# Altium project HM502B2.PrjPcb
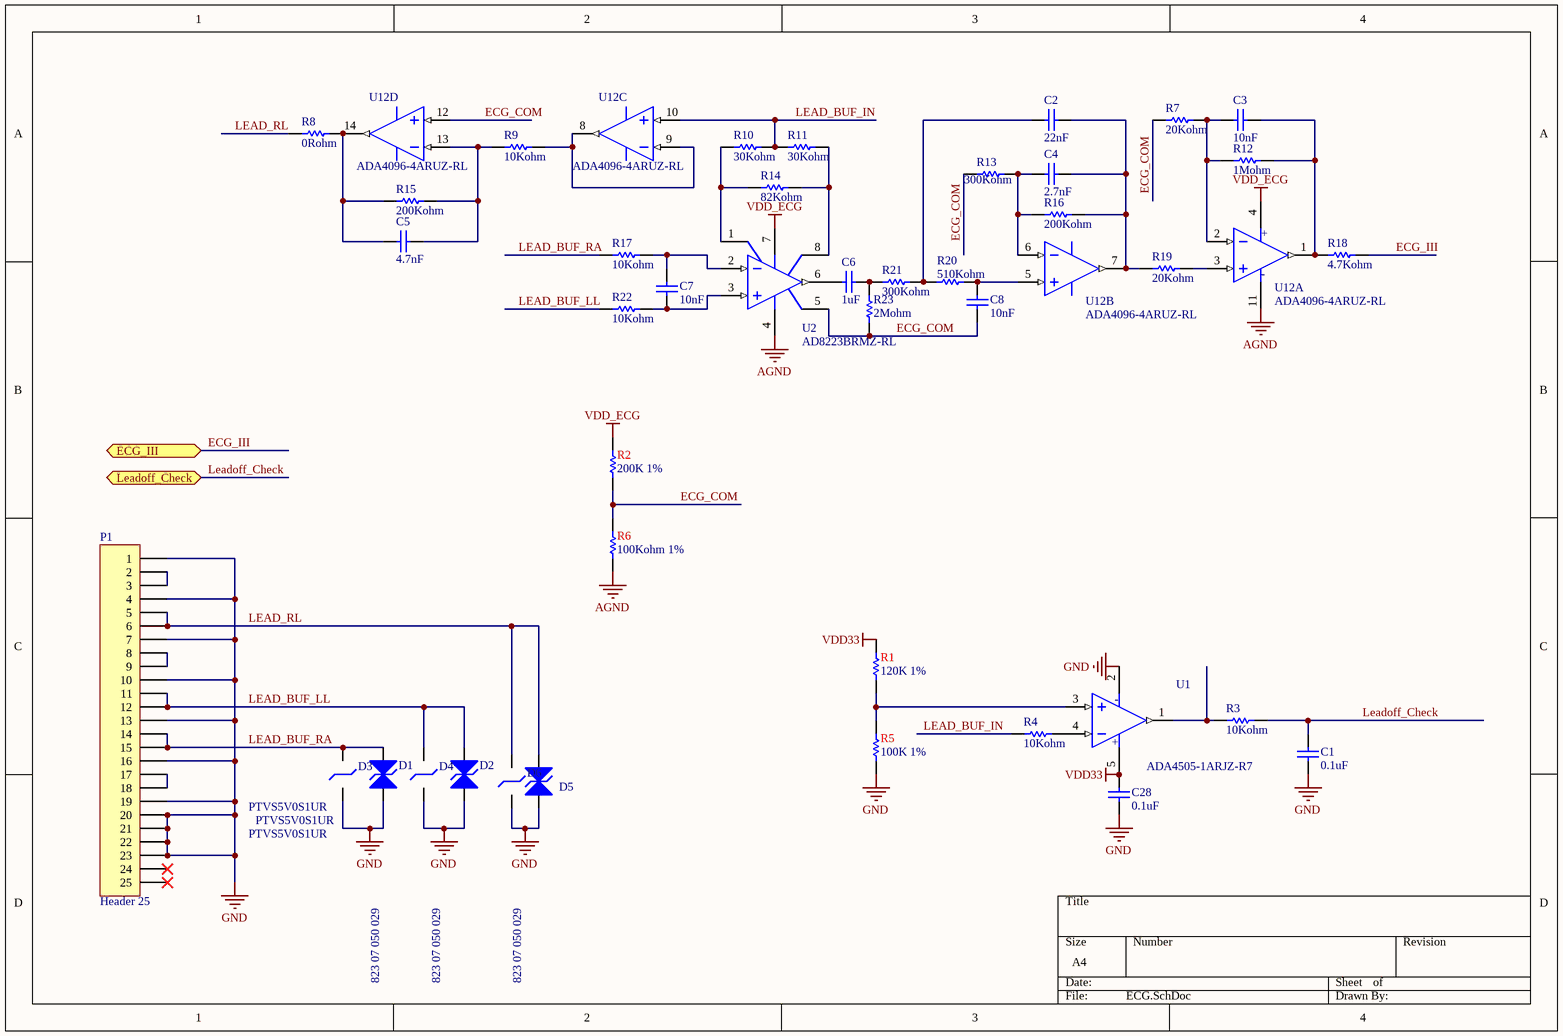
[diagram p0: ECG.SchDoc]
4 sheets, 138 parts. Net scope: flat (ports and power ports of the same name join across sheets).
Board files: HM502B2.PcbDoc, HM502B2拼板.PcbDoc
Sheets:
  ECG.SchDoc
  MCU.SchDoc
  POWER.SchDoc
  UART_BT.SchDoc

## Sheet ECG.SchDoc
size A4

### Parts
C1  0.1uF  [C0402]
C2  22nF  [C0402]
C3  10nF  [C0402]
C4  2.7nF  [C0402]
C5  4.7nF  [C0402]
C6  1uF  [C0402]
C7  10nF  [C0402]
C8  10nF  [C0402]
C28  0.1uF  [C0402]
D1  823 07 050 029  [R0402]
D2  823 07 050 029  [R0402]
D3  PTVS5V0S1UR  [SOD123]
D4  PTVS5V0S1UR  [SOD123]
D5  823 07 050 029  [R0402]
D6  PTVS5V0S1UR  [SOD123]
P1  Header 25  [mini-HDMI_post]
R1  120K 1%  [R0402]
R2  200K 1%  [R0402]
R3  10Kohm  [R0402]
R4  10Kohm  [R0402]
R5  100K 1%  [R0402]
R6  100Kohm 1%  [R0402]
R7  20Kohm  [R0402]
R8  0Rohm  [R0402]
R9  10Kohm  [R0402]
R10  30Kohm  [R0402]
R11  30Kohm  [R0402]
R12  1Mohm  [R0402]
R13  300Kohm  [R0402]
R14  82Kohm  [R0402]
R15  200Kohm  [R0402]
R16  200Kohm  [R0402]
R17  10Kohm  [R0402]
R18  4.7Kohm  [R0402]
R19  20Kohm  [R0402]
R20  510Kohm  [R0402]
R21  300Kohm  [R0402]
R22  10Kohm  [R0402]
R23  2Mohm  [R0402]
U1  ADA4505-1ARJZ-R7  [SOT-23-5]
U2  AD8223BRMZ-RL  [MSOP-8]
U12  ADA4096-4ARUZ-RL  [TSSOP-14]  (parts A,B,C,D of 4)

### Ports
ECG_III, Leadoff_Check

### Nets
AGND: R6.1 U2.4(V-) U12.11(V-)
GND: C1.2 C28.2 D1.2(K) D2.1(K) D3.1(K) D4.1(K) D5.1(K) D6.1(K) P1.1 P1.4 P1.7 P1.10 P1.13 P1.16 P1.19 P1.20 P1.21 P1.22 P1.23 R5.1 U1.2(V-)
VDD33: C28.1 R1.2 U1.5(V+)
VDD_ECG: R2.2 U2.7(V+) U12.4(V+)
ECG_COM: C8.2 R2.1 R6.2 R7.1 R13.1 R23.1 U2.5(NC) U12.12(IN+)
ECG_III: R18.2 ; port ECG_III
LEAD_BUF_IN: R4.1 R10.2 R11.1 U12.10(IN+)
LEAD_BUF_LL: D2.2(K) D4.2(K) P1.11 P1.12 R22.1
LEAD_BUF_RA: D1.1(K) D3.2(K) P1.14 P1.15 R17.1
LEAD_RL: D5.2(K) D6.2(K) P1.5 P1.6 R8.1
Leadoff_Check: C1.1 R3.2 ; port Leadoff_Check
NetC2_1: C2.1 R20.1 R21.2
NetC2_2: C2.2 C4.2 R16.2 R19.1 U12.7(OUT)
NetC3_1: C3.1 R7.2 R12.1 U12.2(IN-)
NetC3_2: C3.2 R12.2 R18.1 U12.1(OUT)
NetC4_1: C4.1 R13.2 R16.1 U12.6(IN-)
NetC5_1: C5.1 R8.2 R15.1 U12.14(OUT)
NetC5_2: C5.2 R9.1 R15.2 U12.13(IN-)
NetC6_1: C6.1 U2.6(OUT)
NetC6_2: C6.2 R21.1 R23.2
NetC7_1: C7.1 R17.2 U2.2(IN-)
NetC7_2: C7.2 R22.2 U2.3(IN+)
NetC8_1: C8.1 R20.2 U12.5(IN+)
NetP1_2: P1.2 P1.3
NetP1_8: P1.8 P1.9
NetP1_17: P1.17 P1.18
NetR1_1: R1.1 R5.2 U1.3(IN+)
NetR3_1: R3.1 U1.1(OUT)
NetR4_2: R4.2 U1.4(IN-)
NetR9_2: R9.2 U12.8(OUT) U12.9(IN-)
NetR10_1: R10.1 R14.1 U2.1(VOSTRIM)
NetR11_2: R11.2 R14.2 U2.8(VOSTRIM)
NetR19_2: R19.2 U12.3(IN+)

Not connected (* = marked no-connect by the designer): P1 24* 25*

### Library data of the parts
C1 C3 C7 C8 C28 = Cap Semi: 0402,50V,10nF,10%,X7R,0.55mm; 名称: 贴片电容; 物料编号: 11U2103K00; 生产厂家型号: CC0402KRX7R9BB103; 生产厂家: 国巨
C2 = Cap Semi: 0402,10V,22nF,10% ,X5R,0.55mm; 名称: 贴片电容; 物料编号: 11E2223K0F; 生产厂家型号: GRM155R61A223KA01D; 生产厂家: MURATA
C4 = Cap Semi: 0402,50V,2.7nF,10%,X7R,0.55mm; 名称: 贴片电容; 物料编号: 11U2272K00; 生产厂家型号: CC0402KRX7R9BB272; 生产厂家: 国巨
C5 = Cap Semi: 0402,50V,4.7nF,10% ,X7R,0.55mm; 名称: 贴片电容; 物料编号: 11U2472K00; 生产厂家型号: CC0402KRX7R9BB472; 生产厂家: 国巨
C6 = Cap Semi: 0402,16V,1uF,10%,X5R,0.55mm; 名称: 贴片电容; 物料编号: 11E2105K00; 生产厂家型号: CC0402KRX5R7BB105; 生产厂家: 国巨
D1 D2 D5 = TPD1E10B06: ESD,0402,5V,0.2pF,0.05uA; 物料编号: 141D002837; 生产厂家: WE
D3 D4 D6 = ESD7951S-D-92833: TVS ESD,SOD923,5V,0.5pF,1uA; 名称: 贴片TVS管; 备注: Vrwm=5V,VBR (V)=6.2,VCL (V)=9.2,IRM (μA)=5; 生产厂家: NXP
P1 = Header 25: Header, 25-Pin
R1-R6 R8 R9 R17 R22 = Res Semi: 0402,10Kohm,1%,1/16W,0.40mm; 名称: 贴片电阻; 物料编号: 1121002F00; 生产厂家型号: RC0402FR-0710KL; 生产厂家: 国巨
R7 R19 = Res Semi: 0402,20Kohm,1%,1/16W,0.40mm; 名称: 贴片电阻; 物料编号: 1122002F00; 生产厂家型号: RC0402FR-0720KL; 生产厂家: 国巨
R10 R11 = Res Semi: 0402,30Kohm,1%,1/16W,0.40mm; 名称: 贴片电阻; 物料编号: 1123002F00; 生产厂家型号: RC0402FR-0730KL; 生产厂家: 国巨
R12 = Res Semi: 0402,1Mohm,1%,1/16W,0.40mm; 名称: 贴片电阻; 物料编号: 1121004F00; 生产厂家型号: RC0402FR-071ML; 生产厂家: 国巨
R13 R21 = Res Semi: 0402,300Kohm,1%,1/16W,0.40mm; 名称: 贴片电阻; 物料编号: 1123003F00; 生产厂家型号: RC0402FR-07300KL; 生产厂家: 国巨
R14 = Res Semi: 0402,82Kohm,1%,1/16W,0.40mm; 名称: 贴片电阻; 物料编号: 1128202F00; 生产厂家型号: RC0402FR-0782KL; 生产厂家: 国巨
R15 R16 = Res Semi: 0402,200Kohm,1%,1/16W,0.40mm; 名称: 贴片电阻; 物料编号: 1122003F00; 生产厂家型号: RC0402FR-07200KL; 生产厂家: 国巨
R18 = Res Semi: 0402,3Kohm,1%,1/16W,0.40mm; 名称: 贴片电阻; 物料编号: 1124701J00; 生产厂家型号: RC0402JR-074K7L; 生产厂家: 国巨
R20 = Res Semi: 0402,510Kohm,1%,1/16W,0.40mm; 名称: 贴片电阻; 物料编号: 1125103F00; 生产厂家型号: RC0402FR-07510KL; 生产厂家: 国巨
R23 = Res Semi: 0402,2Mohm,1%,1/16W,0.40mm; 名称: 贴片电阻; 物料编号: 1122004F00; 生产厂家型号: RC0402FR-072ML; 生产厂家: 国巨
U1 = OPA348: 50KHz,10uA,SOT-23-5; 名称: 轨至轨运算放大器; 物料编号: 13CB02220X; 生产厂家: ADI
U2 = OP05CP: 单电源、轨到轨、仪表放大器,MSOP-8; 名称: 仪表放大器; 物料编号: 13CC02190X; 生产厂家: ADI
U12 = LP324: 4通道,微功耗,TSSOP-14; 名称: 运放; 物料编号: 13C302200X; 生产厂家: ADI

## Sheet MCU.SchDoc
size A3
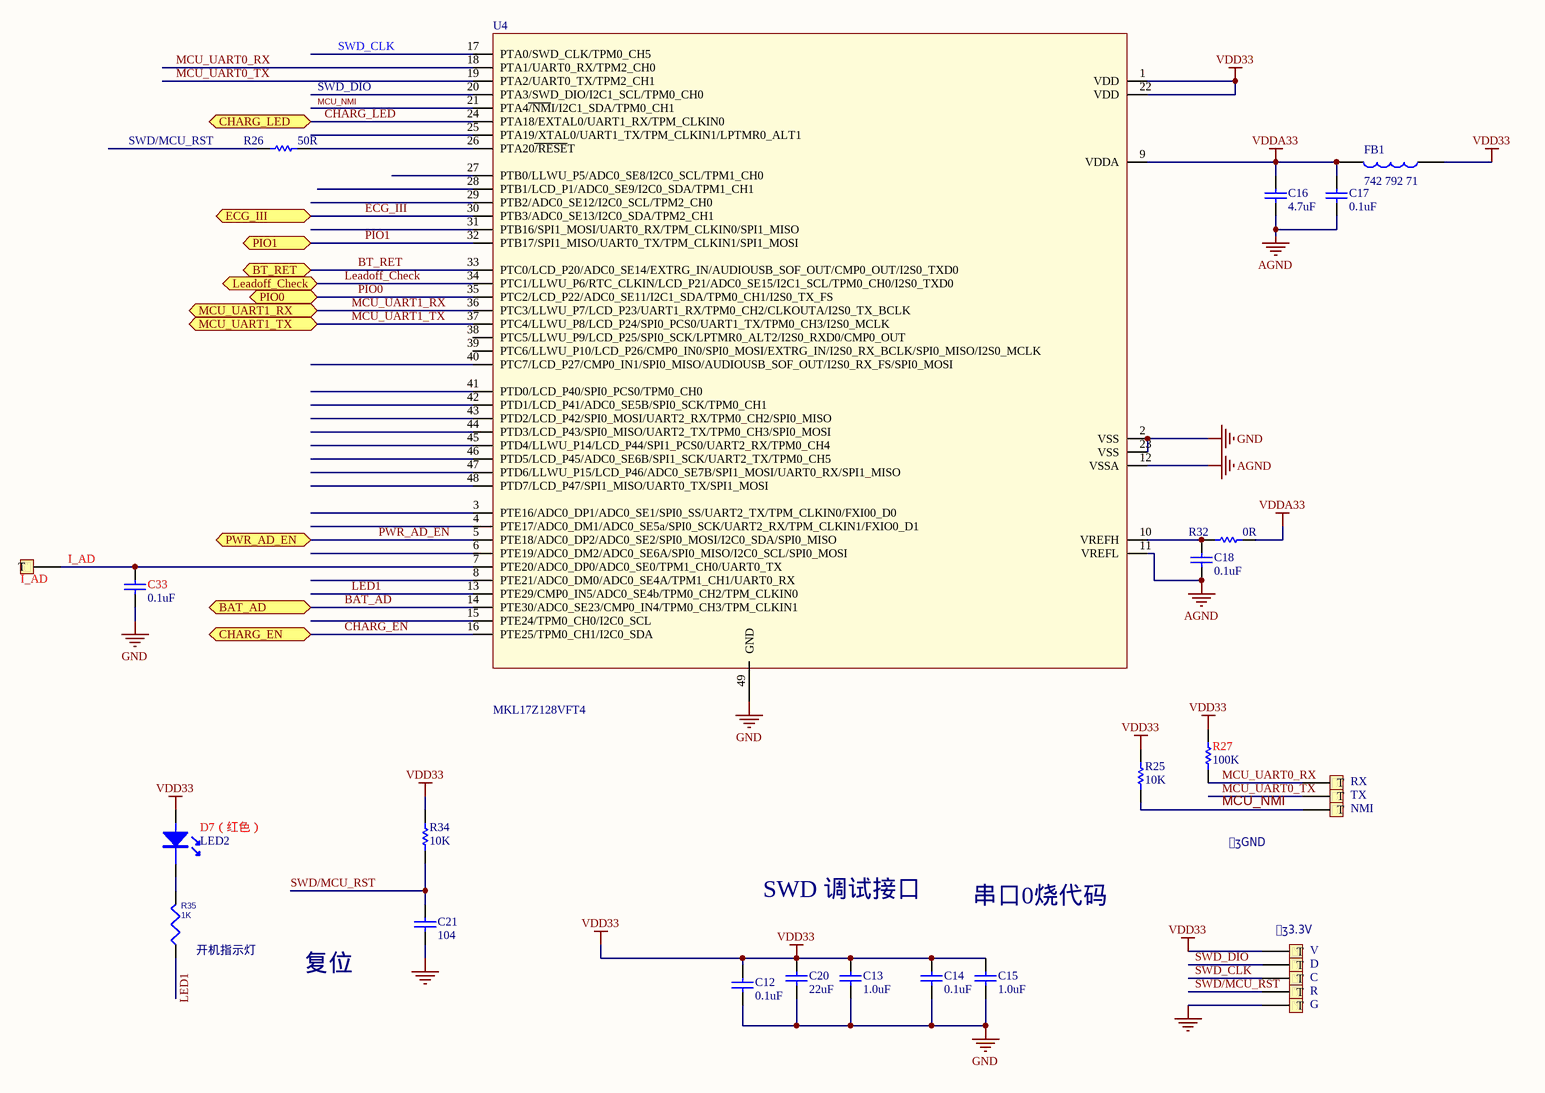
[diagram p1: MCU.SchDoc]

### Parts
C  TEST  [TP - 1.27mm]  (value not drawn)
C12  0.1uF  [C0402]
C13  1.0uF  [C0402]
C14  0.1uF  [C0402]
C15  1.0uF  [C0402]
C16  4.7uF  [C0805]
C17  0.1uF  [C0402]
C18  0.1uF  [C0402]
C20  22uF  [C0805]
C21  104  [C0402]
C33  0.1uF  [C0402]
D  TEST  [TP - 1.27mm]  (value not drawn)
D7（红色）  LED2  [LED0603]
FB1  742 792 71  [FB0402]
G  TEST  [TP - 1.27mm]  (value not drawn)
I_AD  TEST  [TP - 1.27mm]  (value not drawn)
NMI  TEST  [TP - 1.27mm]  (value not drawn)
R  TEST  [TP - 1.27mm]  (value not drawn)
R25  10K  [R0402]
R26  50R  [R0402]
R27  100K  [R0402]
R32  0R  [R0402]
R34  10K  [R0402]
R35  1K  [R0402]
RX  TEST  [TP - 1.27mm]  (value not drawn)
TX  TEST  [TP - 1.27mm]  (value not drawn)
U4  MKL17Z128VFT4  [QFN48-0707-.5-A]
V  TEST  [TP - 1.27mm]  (value not drawn)

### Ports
BAT_AD, BT_RET, CHARG_EN, CHARG_LED, ECG_III, Leadoff_Check, MCU_UART1_RX, MCU_UART1_TX, PIO0, PIO1, PWR_AD_EN

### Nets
AGND: C16.2 C17.2 C18.2 U4.11(VREFL) U4.12(VSSA)
GND: C12.2 C13.2 C14.2 C15.2 C20.2 C21.2 C33.2 G.0(T) U4.2(VSS) U4.23(VSS) U4.49(GND)
VDD33: C12.1 C13.1 C14.1 C15.1 C20.1 D7（红色）.1 FB1.2 R25.1 R27.1 R34.2 U4.1(VDD) U4.22(VDD) V.0(T)
VDDA33: C16.1 C17.1 FB1.1 R32.2 U4.9(VDDA)
BAT_AD: U4.14(PTE30/ADC0_SE23/CMP0_IN4/TPM0_CH3/TPM_CLKIN1) ; port BAT_AD
BT_RET: U4.33(PTC0/LCD_P20/ADC0_SE14/EXTRG_IN/AUDIOUSB_SOF_OUT/CMP0_OUT/I2S0_TXD0) ; port BT_RET
CHARG_EN: U4.16(PTE25/TPM0_CH1/I2C0_SDA) ; port CHARG_EN
CHARG_LED: U4.24(PTA18/EXTAL0/UART1_RX/TPM_CLKIN0) ; port CHARG_LED
ECG_III: U4.30(PTB3/ADC0_SE13/I2C0_SDA/TPM2_CH1) ; port ECG_III
I_AD: C33.1 I_AD.0(T) U4.7(PTE20/ADC0_DP0/ADC0_SE0/TPM1_CH0/UART0_TX)
Leadoff_Check: U4.34(PTC1/LLWU_P6/RTC_CLKIN/LCD_P21/ADC0_SE15/I2C1_SCL/TPM0_CH0/I2S0_TXD0) ; port Leadoff_Check
LED1: R35.1 U4.13(PTE29/CMP0_IN5/ADC0_SE4b/TPM0_CH2/TPM_CLKIN0)
MCU_NMI: NMI.0(T) R25.2 U4.21(PTA4~{/NM}I/I2C1_SDA/TPM0_CH1)
MCU_UART0_RX: R27.2 RX.0(T) U4.18(PTA1/UART0_RX/TPM2_CH0)
MCU_UART0_TX: TX.0(T) U4.19(PTA2/UART0_TX/TPM2_CH1)
MCU_UART1_RX: U4.36(PTC3/LLWU_P7/LCD_P23/UART1_RX/TPM0_CH2/CLKOUTA/I2S0_TX_BCLK) ; port MCU_UART1_RX
MCU_UART1_TX: U4.37(PTC4/LLWU_P8/LCD_P24/SPI0_PCS0/UART1_TX/TPM0_CH3/I2S0_MCLK) ; port MCU_UART1_TX
PIO0: U4.35(PTC2/LCD_P22/ADC0_SE11/I2C1_SDA/TPM0_CH1/I2S0_TX_FS) ; port PIO0
PIO1: U4.32(PTB17/SPI1_MISO/UART0_TX/TPM_CLKIN1/SPI1_MOSI) ; port PIO1
PWR_AD_EN: U4.5(PTE18/ADC0_DP2/ADC0_SE2/SPI0_MOSI/I2C0_SDA/SPI0_MISO) ; port PWR_AD_EN
SWD/MCU_RST: C21.1 R.0(T) R26.1 R34.1
SWD_CLK: C.0(T) U4.17(PTA0/SWD_CLK/TPM0_CH5)
SWD_DIO: D.0(T) U4.20(PTA3/SWD_DIO/I2C1_SCL/TPM0_CH0)
NetC18_1: C18.1 R32.1 U4.10(VREFH)
NetD7（红色）_2: D7（红色）.2 R35.2
NetR26_2: R26.2 U4.26(PTA20~{/RESE}T)

Not connected (* = marked no-connect by the designer): U4 3(PTE16/ADC0_DP1/ADC0_SE1/SPI0_SS/UART2_TX/TPM_CLKIN0/FXI00_D0) 4(PTE17/ADC0_DM1/ADC0_SE5a/SPI0_SCK/UART2_RX/TPM_CLKIN1/FXIO0_D1) 6(PTE19/ADC0_DM2/ADC0_SE6A/SPI0_MISO/I2C0_SCL/SPI0_MOSI) 8(PTE21/ADC0_DM0/ADC0_SE4A/TPM1_CH1/UART0_RX) 15(PTE24/TPM0_CH0/I2C0_SCL) 25(PTA19/XTAL0/UART1_TX/TPM_CLKIN1/LPTMR0_ALT1) 27(PTB0/LLWU_P5/ADC0_SE8/I2C0_SCL/TPM1_CH0) 28(PTB1/LCD_P1/ADC0_SE9/I2C0_SDA/TPM1_CH1) 29(PTB2/ADC0_SE12/I2C0_SCL/TPM2_CH0) 31(PTB16/SPI1_MOSI/UART0_RX/TPM_CLKIN0/SPI1_MISO) 38(PTC5/LLWU_P9/LCD_P25/SPI0_SCK/LPTMR0_ALT2/I2S0_RXD0/CMP0_OUT) 39(PTC6/LLWU_P10/LCD_P26/CMP0_IN0/SPI0_MOSI/EXTRG_IN/I2S0_RX_BCLK/SPI0_MISO/I2S0_MCLK) 40(PTC7/LCD_P27/CMP0_IN1/SPI0_MISO/AUDIOUSB_SOF_OUT/I2S0_RX_FS/SPI0_MOSI) 41(PTD0/LCD_P40/SPI0_PCS0/TPM0_CH0) 42(PTD1/LCD_P41/ADC0_SE5B/SPI0_SCK/TPM0_CH1) 43(PTD2/LCD_P42/SPI0_MOSI/UART2_RX/TPM0_CH2/SPI0_MISO) 44(PTD3/LCD_P43/SPI0_MISO/UART2_TX/TPM0_CH3/SPI0_MOSI) 45(PTD4/LLWU_P14/LCD_P44/SPI1_PCS0/UART2_RX/TPM0_CH4) 46(PTD5/LCD_P45/ADC0_SE6B/SPI1_SCK/UART2_TX/TPM0_CH5) 47(PTD6/LLWU_P15/LCD_P46/ADC0_SE7B/SPI1_MOSI/UART0_RX/SPI1_MISO) 48(PTD7/LCD_P47/SPI1_MISO/UART0_TX/SPI1_MOSI)

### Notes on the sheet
- ˿ӡGND
- SWD 调试接口
- 串口0烧代码
- (near V) ˿ӡ3.3V
- (near R35) 开机指示灯
- 复位

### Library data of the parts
C12 C14 C17 C18 = Cap Semi: 0402,50V,33pF,5%,C0G,0.55mm; 名称: 贴片电容; 物料编号: 11E2104A00; 生产厂家型号: CC0402ZRY5V7BB104; 生产厂家: 国巨; 备注: 0402C，100nF(104)，16V，20%
C13 C15 = Cap Semi: 0402,50V,33pF,5%,C0G,0.55mm; 名称: 贴片电容; 物料编号: 11E2105K00; 生产厂家型号: CC0402KRX5R7BB105; 生产厂家: 国巨; 备注: 0402C，X5R，1uF，16V，0.5mm±0.005，±10%
C16 C20 C21 = Cap Semi: 0402,50V,33pF,5%,C0G,0.55mm; 名称: 贴片电容; 生产厂家: MURATA
C33 = Cap Semi: as C1 on sheet ECG
FB1 = FB: 备注: 120ohm@100MHz,0402,0.55mm,500mA; 物料编码: 1T12121C37; 生产厂家: WE; 名称: 贴片磁珠
R25 R27 R34 = Res Semi: as R1 on sheet ECG
R26 R32 = Res Semi: 0402,10Kohm,1%,1/16W,0.40mm; 名称: 贴片电阻; 生产厂家: 国巨
R35 = R_Dup3: Right: 20; Bottom: 30
U4 = MKL17Z128VFT4: 生产厂家: FreeScale; 名称: MCU

## Sheet POWER.SchDoc
size A4; Organization: Altium Limited; Address1: L3, 12a Rodborough Rd; Address2: Frenchs Forest; Address3: NSW; Address4: Australia 2086
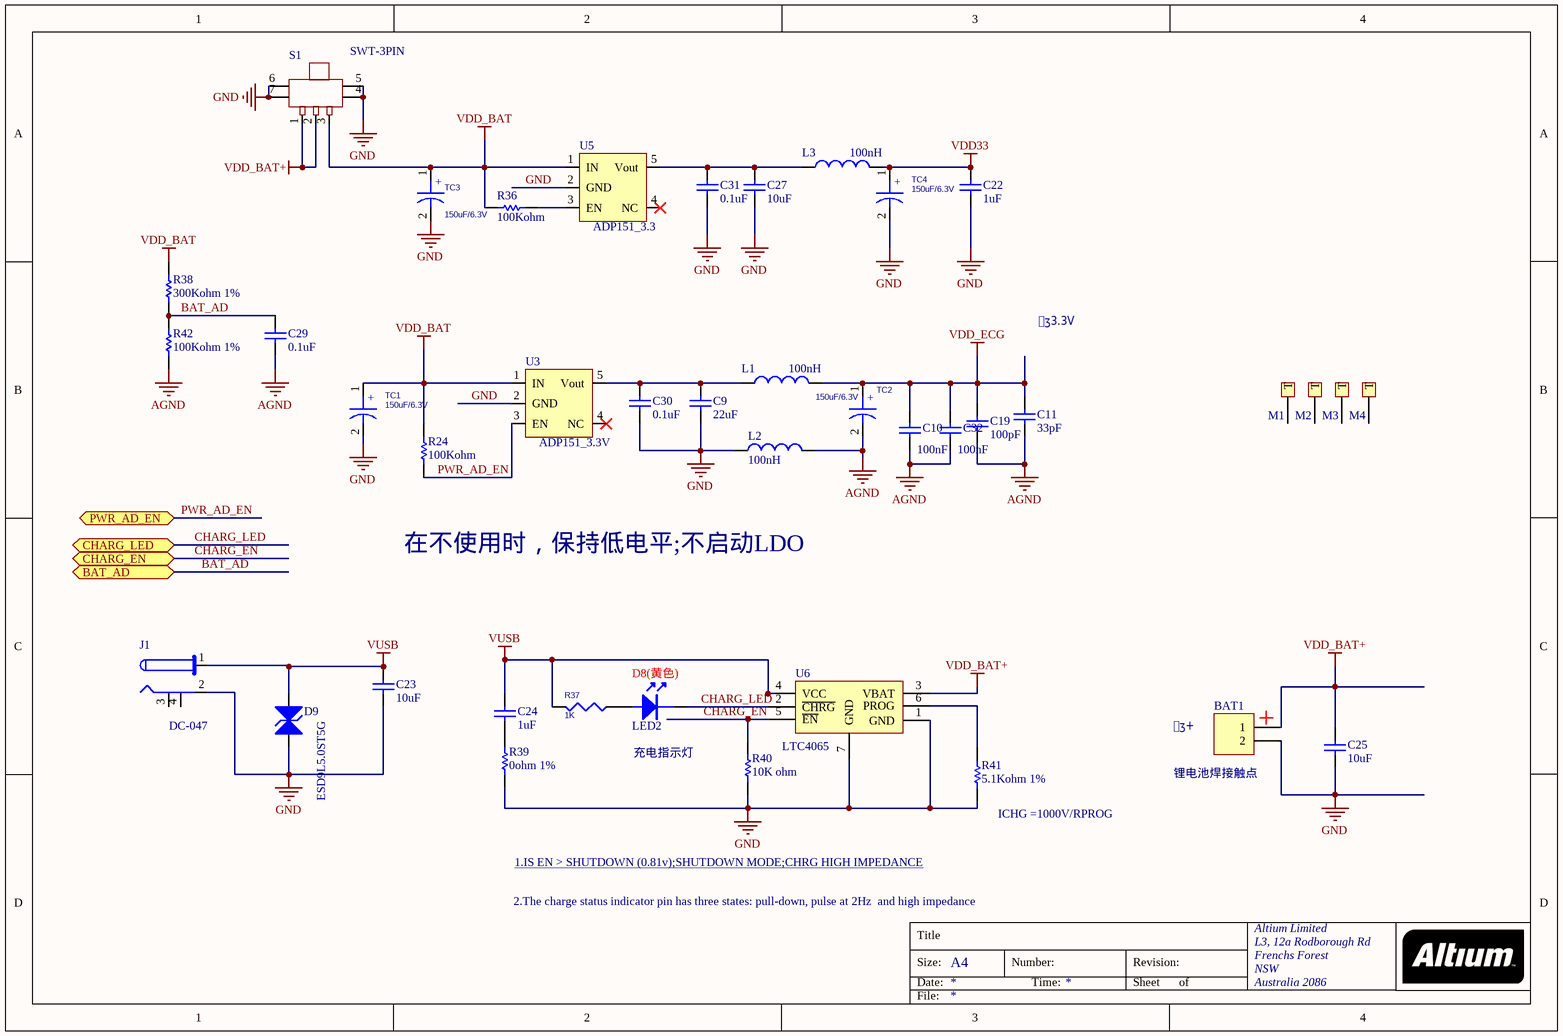
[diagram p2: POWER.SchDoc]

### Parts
BAT1  锂电池焊接触点  [R1210]
C9  22uF  [C0805]
C10  100nF  [C0402]
C11  33pF  [C0402]
C19  100pF  [C0402]
C22  1uF  [C0402]
C23  10uF  [C0805]
C24  1uF  [C0402]
C25  10uF  [C0805]
C27  10uF  [C0805]
C29  0.1uF  [C0402]
C30  0.1uF  [C0402]
C31  0.1uF  [C0402]
C32  100nF  [C0402]
D8(黄色)  LED2  [LED0603]
D9  ESD9L5.0ST5G  [SOD923]
J1  DC-047  [DC-047]
L1  100nH  [L0805]
L2  100nH  [L0805]
L3  100nH  [L0805]
M1  TEST  [MARK]  (value not drawn)
M2  TEST  [MARK]  (value not drawn)
M3  TEST  [MARK]  (value not drawn)
M4  TEST  [MARK]  (value not drawn)
R24  100Kohm  [R0402]
R36  100Kohm  [R0402]
R37  1K  [R0402]
R38  300Kohm 1%  [R0402]
R39  0ohm 1%  [R0402]
R40  10K ohm  [R0402]
R41  5.1Kohm 1%  [R0402]
R42  100Kohm 1%  [R0402]
S1  SWT-3PIN  [SW-3PIN]
TC1  150uF/6.3V  [3528]
TC2  150uF/6.3V  [3528]
TC3  150uF/6.3V  [3528]
TC4  150uF/6.3V  [3528]
U3  ADP151_3.3V  [SOT-23-5]
U5  ADP151_3.3  [SOT-23-5]
U6  LTC4065

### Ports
BAT_AD, CHARG_EN, CHARG_LED, PWR_AD_EN

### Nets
AGND: C10.2 C11.2 C19.2 C29.2 C32.2 L2.1 R42.1 TC2.2
GND: BAT1.2 C9.2 C22.2 C23.2 C25.2 C27.2 C30.2 C31.2 D9.1(K) J1.2 L2.2 R39.1 R40.1 R41.1 S1.4 S1.5 S1.6 S1.7 TC1.2 TC3.2 TC4.2 U3.2(GND) U5.2(GND) U6.1(GND) U6.7(GND)
VDD33: C22.1 L3.2 TC4.1
VDD_BAT: R24.1 R36.2 R38.2 S1.3 TC1.1 TC3.1 U3.1(IN) U5.1(IN)
VDD_BAT+: BAT1.1 C25.1 S1.1 S1.2 U6.3(VBAT)
VDD_ECG: C10.1 C11.1 C19.1 C32.1 L1.2 TC2.1
VUSB: C23.1 C24.1 D9.2(K) J1.1 R37.2 U6.4(VCC)
BAT_AD: C29.1 R38.1 R42.2 ; port BAT_AD
CHARG_EN: R40.2 U6.5(~{EN}) ; port CHARG_EN
CHARG_LED: D8(黄色).2 U6.2(~{CHRG}) ; port CHARG_LED
PWR_AD_EN: R24.2 U3.3(EN) ; port PWR_AD_EN
NetC9_1: C9.1 C30.1 L1.1 U3.5(Vout)
NetC24_2: C24.2 R39.2
NetC27_1: C27.1 C31.1 L3.1 U5.5(Vout)
NetD8(黄色)_1: D8(黄色).1 R37.1
NetR36_1: R36.1 U5.3(EN)
NetR41_2: R41.2 U6.6(PROG)

Not connected (* = marked no-connect by the designer): J1 3 4; M1 0(T); M2 0(T); M3 0(T); M4 0(T); U3 4(NC)*; U5 4(NC)*

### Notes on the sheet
- ˿ӡ3.3V
- 在不使用时，保持低电平;不启动LDO
- 充电指示灯
- ˿ӡ+
- (near R41) ICHG =1000V/RPROG
- 2.The charge status indicator pin has three states: pull-down, pulse at 2Hz  and high impedance
- 1.IS EN > SHUTDOWN (0.81v);SHUTDOWN MODE;CHRG HIGH IMPEDANCE

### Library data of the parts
BAT1 = Header 2: Header, 2-Pin
C9 C22 C23 C25 C27 C31 = Cap Semi: as C16 on sheet MCU
C10 C32 = Cap Semi: 0402,16V,100nF,10%,X5R,0.55mm; 名称: 贴片电容; 物料编号: 11EG104K0F; 生产厂家型号: GRM155R61C104KA88D; 生产厂家: MURATA
C11 C19 = Cap Semi: 0402,50V,33pF,5%,C0G,0.55mm; 名称: 贴片电容; 物料编号: 11UG330J0F; 生产厂家型号: GRM1555C1H330JA01D; 生产厂家: MURATA
C24 C30 = Cap Semi: as C1 on sheet ECG
C29 = Cap Semi: as C12 on sheet MCU
D9 = TPD1E10B06: ESD,0402,5V,0.2pF,0.05uA; 物料编号: 141D00192W; 生产厂家: WE
J1 = DC-047: Value: DC_047; 备注: SMT,9*6.4*4.8mm,2Pin,DC电源插座,; 物料编号: 1AX0409861; 生产厂家: 东莞科美
L1-L3 = Inductor
R24 R36 R39-R42 = Res Semi: as R1 on sheet ECG
R37 = R_Dup3: Right: 20; Bottom: 30
R38 = Res Semi: as R26 on sheet MCU
S1 = SWT-3PIN: 物料标号: 1R40300289; Value: MK-12C02; 备注: 6.6*2.74*1.4mm，开关长度1.3mm，2个φ0.74mm，3mm间距定位孔，DC50V 0.3A，7Pin ，贴片开关; 生产厂家: 佳龙; 名称: 贴片开关
TC1-TC4 = CAP_TC_Dup3: 备注: 150uF,6.3V,70mohm,3258    12C8157M0C; 物料编号: 12C8157M0C; 生产厂家: Kemet; 生产厂家型号: T520M157M006ATE070; 名称: 钽电容
U3 = ADP151_TSDT: 备注: Ultralow Noise, 200 mA,Input voltage range: 2.2 V to 5.5 V; 生产厂家型号: ADP151AUJZ-3.3-R7; 生产厂家: ADI; 名称: LDO电源
U5 = ADP151_TSDT: 备注: Ultralow Noise, 200 mA,Input voltage range: 2.2 V to 5.5 V; 生产厂家型号: ADP151AUJZ-3.3-R7; 生产厂家: ADI

## Sheet UART_BT.SchDoc
size A4; Organization: Altium Limited; Address1: L3, 12a Rodborough Rd; Address2: Frenchs Forest; Address3: NSW; Address4: Australia 2086
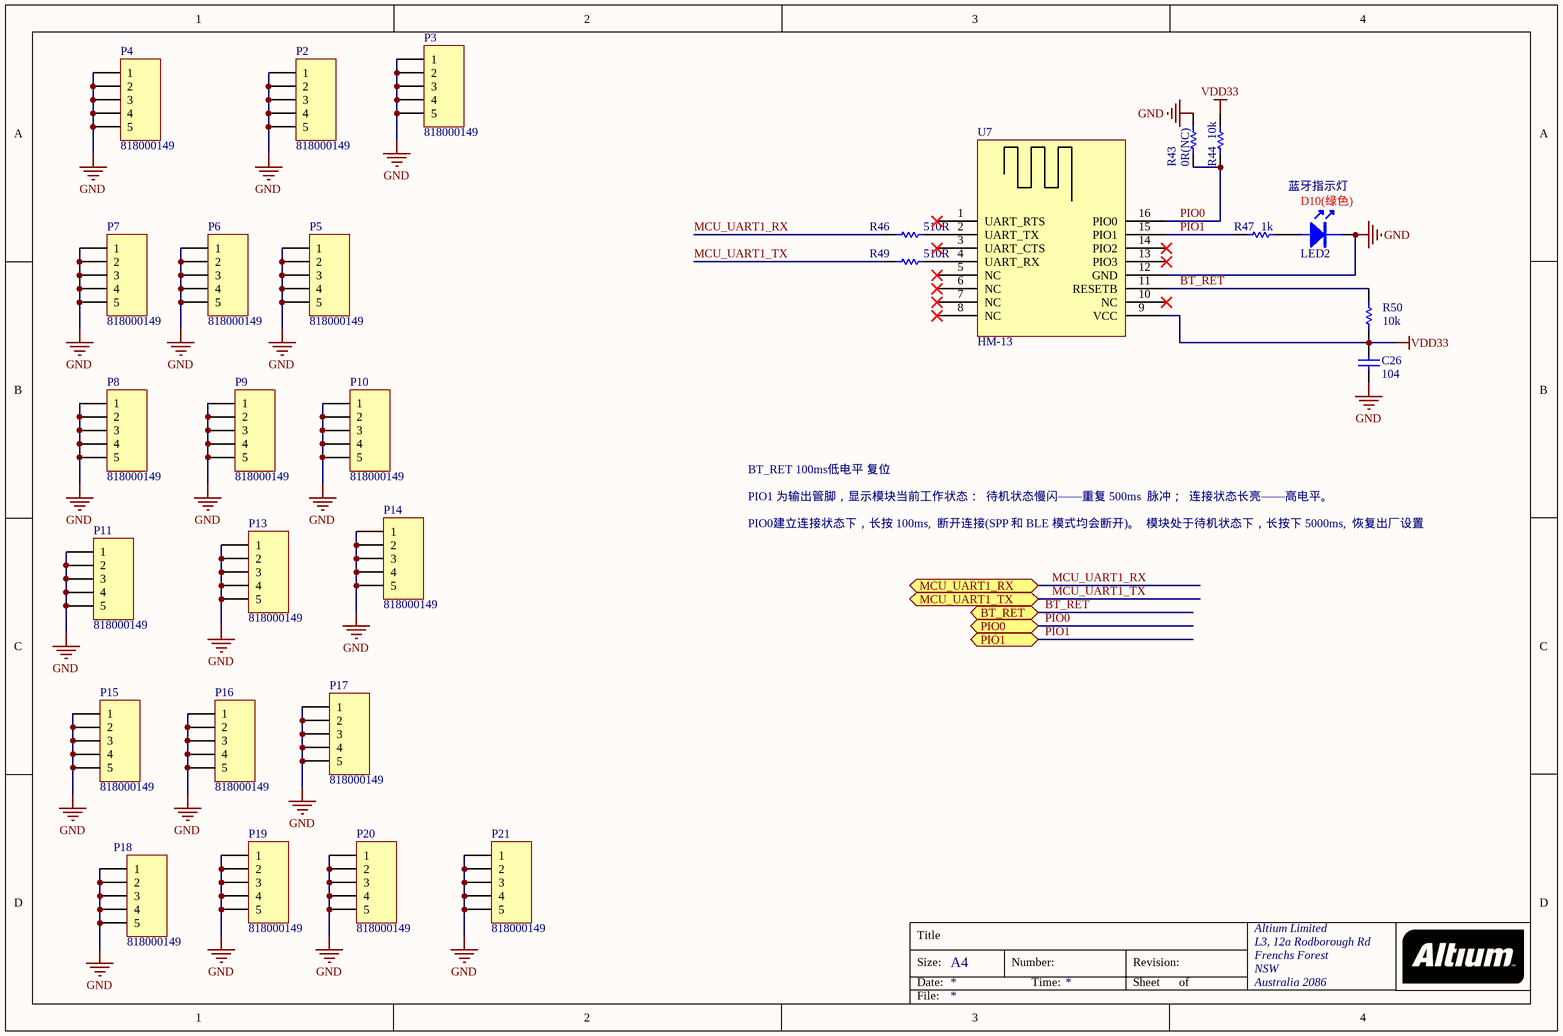
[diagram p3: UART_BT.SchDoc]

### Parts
C26  104  [C0402]
D10(绿色)  LED2  [LED0603]
P2  818000149  [Shield-5pin]
P3  818000149  [Shield-5pin]
P4  818000149  [Shield-5pin]
P5  818000149  [Shield-5pin]
P6  818000149  [Shield-5pin]
P7  818000149  [Shield-5pin]
P8  818000149  [Shield-5pin]
P9  818000149  [Shield-5pin]
P10  818000149  [Shield-5pin]
P11  818000149  [Shield-5pin]
P13  818000149  [Shield-5pin]
P14  818000149  [Shield-5pin]
P15  818000149  [Shield-5pin]
P16  818000149  [Shield-5pin]
P17  818000149  [Shield-5pin]
P18  818000149  [Shield-5pin]
P19  818000149  [Shield-5pin]
P20  818000149  [Shield-5pin]
P21  818000149  [Shield-5pin]
R43  0R(NC)  [R0402]
R44  10k  [R0402]
R46  510R  [R0402]
R47  1k  [R0402]
R49  510R  [R0402]
R50  10k  [R0402]
U7  HM-13  [HM-13]

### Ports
BT_RET, MCU_UART1_RX, MCU_UART1_TX, PIO0, PIO1

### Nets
GND: C26.2 D10(绿色).2 P2.1 P2.2 P2.3 P2.4 P2.5 P3.1 P3.2 P3.3 P3.4 P3.5 P4.1 P4.2 P4.3 P4.4 P4.5 P5.1 P5.2 P5.3 P5.4 P5.5 P6.1 P6.2 P6.3 P6.4 P6.5 P7.1 P7.2 P7.3 P7.4 P7.5 P8.1 P8.2 P8.3 P8.4 P8.5 P9.1 P9.2 P9.3 P9.4 P9.5 P10.1 P10.2 P10.3 P10.4 P10.5 P11.1 P11.2 P11.3 P11.4 P11.5 P13.1 P13.2 P13.3 P13.4 P13.5 P14.1 P14.2 P14.3 P14.4 P14.5 P15.1 P15.2 P15.3 P15.4 P15.5 P16.1 P16.2 P16.3 P16.4 P16.5 P17.1 P17.2 P17.3 P17.4 P17.5 P18.1 P18.2 P18.3 P18.4 P18.5 P19.1 P19.2 P19.3 P19.4 P19.5 P20.1 P20.2 P20.3 P20.4 P20.5 P21.1 P21.2 P21.3 P21.4 P21.5 R43.2 U7.12(GND)
VDD33: C26.1 R44.2 R50.1 U7.9(VCC)
BT_RET: R50.2 U7.11(RESETB) ; port BT_RET
MCU_UART1_RX: R46.1 ; port MCU_UART1_RX
MCU_UART1_TX: R49.1 ; port MCU_UART1_TX
PIO0: R43.1 R44.1 U7.16(PIO0) ; port PIO0
PIO1: R47.2 U7.15(PIO1) ; port PIO1
NetD10(绿色)_1: D10(绿色).1 R47.1
NetR46_2: R46.2 U7.2(UART_TX)
NetR49_2: R49.2 U7.4(UART_RX)

Not connected (* = marked no-connect by the designer): U7 1(UART_RTS)* 3(UART_CTS)* 5(NC)* 6(NC)* 7(NC)* 8(NC)* 10(NC)* 13(PIO3)* 14(PIO2)*

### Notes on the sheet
- 蓝牙指示灯
- PIO1 为输出管脚，显示模块当前工作状态：  待机状态慢闪——重复 500ms  脉冲；  连接状态长亮——高电平。
- BT_RET 100ms低电平 复位
- PIO0建立连接状态下，长按 100ms,  断开连接(SPP 和 BLE 模式均会断开)。  模块处于待机状态下，长按下 5000ms,  恢复出厂设置

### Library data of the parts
C26 = Cap Semi: as C16 on sheet MCU
P2-P11 P13-P21 = Header 5: Header, 5-Pin; 生产厂家: 深圳市电连精密; 备注: 818000149,W0.5; 名称: 屏蔽罩夹子; 物料编号: 1AX041232N
R43 R44 R46 R47 R49 R50 = Res Semi: as R26 on sheet MCU
U7 = HM-13: 备注: V4.0 EDR+BL E；SPP/BLE; 生产厂家: 华茂

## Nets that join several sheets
AGND: ECG (R6.1 U2.4 U12.11), MCU (5 pins), POWER (8 pins)
GND: ECG (21 pins), MCU (11 pins), POWER (25 pins), UART_BT (99 pins)
VDD33: ECG (C28.1 R1.2 U1.5), MCU (13 pins), POWER (C22.1 L3.2 TC4.1), UART_BT (C26.1 R44.2 R50.1 U7.9)
VDD_ECG: ECG (R2.2 U2.7 U12.4), POWER (6 pins)
BAT_AD: MCU (U4.14), POWER (C29.1 R38.1 R42.2)
BT_RET: MCU (U4.33), UART_BT (R50.2 U7.11)
CHARG_EN: MCU (U4.16), POWER (R40.2 U6.5)
CHARG_LED: MCU (U4.24), POWER (D8(黄色).2 U6.2)
ECG_III: ECG (R18.2), MCU (U4.30)
Leadoff_Check: ECG (C1.1 R3.2), MCU (U4.34)
MCU_UART1_RX: MCU (U4.36), UART_BT (R46.1)
MCU_UART1_TX: MCU (U4.37), UART_BT (R49.1)
PIO0: MCU (U4.35), UART_BT (R43.1 R44.1 U7.16)
PIO1: MCU (U4.32), UART_BT (R47.2 U7.15)
PWR_AD_EN: MCU (U4.5), POWER (R24.2 U3.3)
